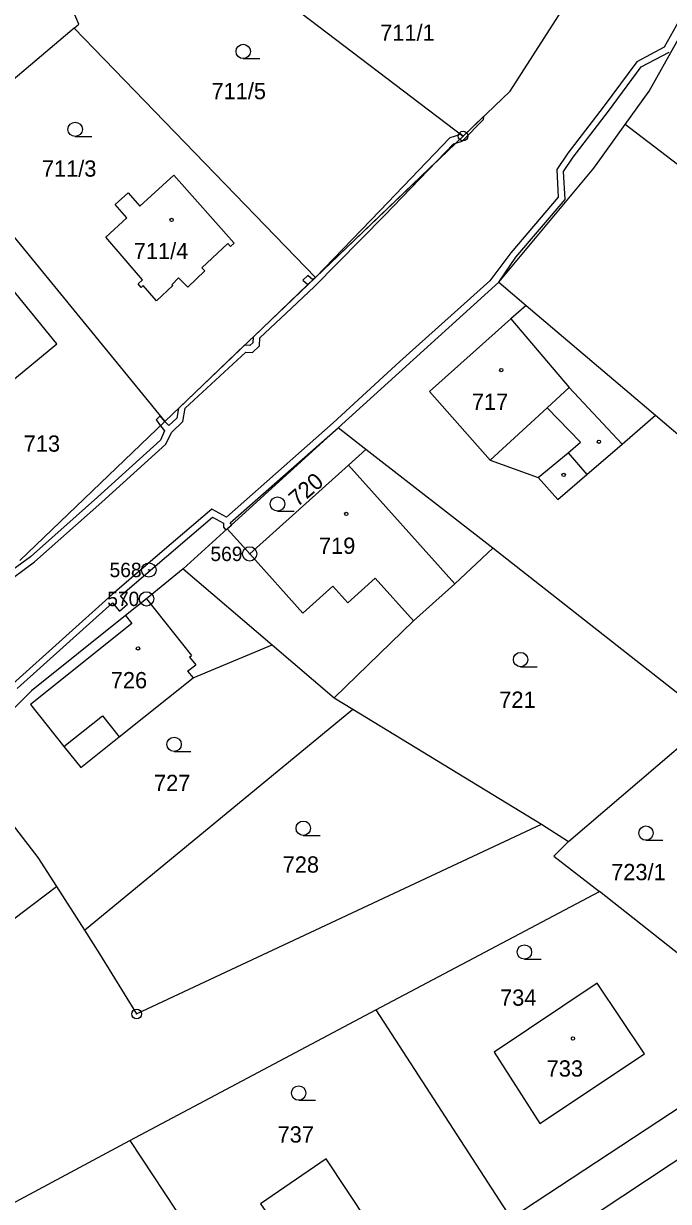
# Model space of a CAD drawing. Extents: x -562167 to -556918, y -1077891 to -1070763.
# Drawn here: x -558509.8 to -558442.5, y -1074168.9 to -1074045.9 of the extents above; entities that cross this region are included whole.
import ezdxf

# ---------------------------------------------------------------- set-up
doc = ezdxf.new("R2010")
doc.units = 0
for name, color, linetype in [('Hranice parcel', 7, 'Continuous'), ('Parcelní čísla', 7, 'Continuous'), ('Vnitřní kresba', 7, 'Continuous'), ('Věcná břemena k části', 7, 'Continuous'), ('Značky bodu BP', 7, 'Continuous'), ('Značky budov', 7, 'Continuous'), ('Značky kultur', 7, 'Continuous')]:
    doc.layers.add(name, color=color, linetype=linetype)

msp = doc.modelspace()

# ---------------------------------------------------------------- linework, layer by layer
at = {"layer": 'Hranice parcel'}
for p, q in [((-558504.53, -1074046.37), (-558518.85, -1074058.43)), ((-558479.36, -1074072.4), (-558504.53, -1074046.37)), ((-558479.36, -1074072.4), (-558463.94, -1074057.63)), ((-558518.85, -1074058.43), (-558495.07, -1074087.45)), ((-558495.07, -1074087.45), (-558479.36, -1074072.4)), ((-558460.22, -1074072.87), (-558476.98, -1074088.11)), ((-558460.22, -1074072.87), (-558457.36, -1074075.31)), ((-558457.36, -1074075.31), (-558443.86, -1074086.79)), ((-558510.2, -1074101.96), (-558495.07, -1074087.45)), ((-558476.98, -1074088.11), (-558488.55, -1074098.65)), ((-558474.08, -1074090.37), (-558476.98, -1074088.11)), ((-558460.85, -1074100.66), (-558474.08, -1074090.37)), ((-558488.55, -1074098.65), (-558493.14, -1074102.82)), ((-558438.83, -1074117.96), (-558460.85, -1074100.66)), ((-558493.14, -1074102.82), (-558483.85, -1074110.77)), ((-558483.85, -1074110.77), (-558477.39, -1074116.29)), ((-558477.39, -1074116.29), (-558475.43, -1074117.49)), ((-558503.45, -1074140.56), (-558475.43, -1074117.49)), ((-558475.43, -1074117.49), (-558455.77, -1074129.5)), ((-558455.77, -1074129.5), (-558452.94, -1074131.31)), ((-558506.36, -1074135.99), (-558503.45, -1074140.56)), ((-558473.04, -1074148.86), (-558449.71, -1074136.51)), ((-558430.4, -1074151.84), (-558449.71, -1074136.51)), ((-558498.72, -1074162.51), (-558473.04, -1074148.86)), ((-558473.04, -1074148.86), (-558458.96, -1074170.63)), ((-558458.96, -1074170.63), (-558430.4, -1074151.84)), ((-558456.42, -1074174.34), (-558426.68, -1074154.67)), ((-558520.86, -1074174.38), (-558498.72, -1074162.51)), ((-558498.72, -1074162.51), (-558483, -1074186.39))]:
    msp.add_line(p, q, dxfattribs=at)
for points in [[(-558463.94, -1074057.63), (-558459.03, -1074052.93), (-558449.24, -1074037.67), (-558444.63, -1074028.15)], [(-558493.98, -1074033.22), (-558482.6, -1074043.39), (-558463.94, -1074057.63)], [(-558504.53, -1074046.37), (-558504.04, -1074045.95), (-558506.35, -1074040.56)], [(-558447.01, -1074056.43), (-558444.52, -1074052.95), (-558438.75, -1074042.6), (-558438.26, -1074041.55)], [(-558460.22, -1074072.87), (-558450.28, -1074060.99), (-558447.01, -1074056.43)], [(-558410.6, -1074103.32), (-558428.61, -1074087.89), (-558420.55, -1074076.56), (-558436.68, -1074064.33), (-558447.01, -1074056.43)], [(-558494.24, -1074073.25), (-558495.93, -1074074.84), (-558497.33, -1074073.25), (-558497.54, -1074073.43), (-558497.85, -1074073.06), (-558497.39, -1074072.65), (-558501.24, -1074068.18), (-558499.03, -1074066.16), (-558500.26, -1074064.78), (-558498.9, -1074063.57), (-558497.67, -1074064.94), (-558494.14, -1074061.72), (-558487.84, -1074068.83), (-558488.2, -1074069.16), (-558488.5, -1074068.85), (-558491.2, -1074071.4), (-558490.9, -1074071.71), (-558492.68, -1074073.4), (-558493.63, -1074072.45), (-558494.34, -1074073.15), (-558494.24, -1074073.25)], [(-558520.15, -1074072.93), (-558519.41, -1074073.85), (-558524.41, -1074077.91), (-558522.76, -1074079.92), (-558522.95, -1074080.08), (-558516.62, -1074087.78), (-558506.33, -1074079.31), (-558512.65, -1074071.63), (-558515.03, -1074068.78)], [(-558457.36, -1074075.31), (-558458.94, -1074076.72), (-558467.46, -1074084.32), (-558461.1, -1074091.47), (-558456.11, -1074093.3), (-558454.04, -1074095.58), (-558451.01, -1074092.97), (-558447.34, -1074089.8), (-558443.86, -1074086.79)], [(-558443.86, -1074086.79), (-558433.98, -1074095.19), (-558411.79, -1074113.59)], [(-558474.08, -1074090.37), (-558475.91, -1074092.01), (-558486.21, -1074101.26), (-558488.55, -1074098.65)], [(-558477.39, -1074116.29), (-558469.1, -1074108.25), (-558464.8, -1074104.38), (-558460.85, -1074100.66)], [(-558493.14, -1074102.82), (-558496.98, -1074105.96), (-558499.17, -1074107.7)], [(-558499.17, -1074107.7), (-558508.98, -1074115.58), (-558516.19, -1074122.81)], [(-558499.17, -1074107.7), (-558498.5, -1074108.54), (-558509.1, -1074116.99), (-558505.6, -1074121.38), (-558503.85, -1074123.57), (-558499.82, -1074120.36), (-558492.12, -1074114.22), (-558483.85, -1074110.77)], [(-558452.94, -1074131.31), (-558438.12, -1074118.61), (-558438.83, -1074117.96)], [(-558513.01, -1074126.92), (-558508.33, -1074132.96), (-558506.36, -1074135.99)], [(-558503.45, -1074140.56), (-558501.88, -1074143.02), (-558498.01, -1074149.31), (-558455.77, -1074129.5)], [(-558452.94, -1074131.31), (-558454.46, -1074132.83), (-558449.71, -1074136.51)], [(-558531.92, -1074156.5), (-558521.73, -1074148.8), (-558518.98, -1074146.71), (-558518.11, -1074147.85), (-558512.56, -1074143.64), (-558513.98, -1074141.77), (-558509.95, -1074138.72), (-558506.36, -1074135.99)], [(-558455.92, -1074160.76), (-558445.02, -1074153.47), (-558449.94, -1074146.1), (-558460.7, -1074153.31), (-558455.92, -1074160.76)], [(-558480.2, -1074180), (-558471.66, -1074174.35), (-558478.22, -1074164.45), (-558485.07, -1074169.15), (-558483.98, -1074170.75), (-558485.58, -1074171.84), (-558480.2, -1074180)]]:
    msp.add_lwpolyline(points, dxfattribs=at)
at = {"layer": 'Vnitřní kresba'}
for p, q in [((-558458.94, -1074076.72), (-558452.85, -1074083.87)), ((-558455.16, -1074086), (-558452.85, -1074083.87)), ((-558452.85, -1074083.87), (-558447.34, -1074089.8)), ((-558461.1, -1074091.47), (-558455.16, -1074086)), ((-558455.16, -1074086), (-558451.68, -1074089.58)), ((-558452.97, -1074090.7), (-558451.68, -1074089.58)), ((-558456.11, -1074093.3), (-558452.97, -1074090.7)), ((-558452.97, -1074090.7), (-558451.01, -1074092.97)), ((-558475.91, -1074092.01), (-558464.8, -1074104.38)), ((-558486.21, -1074101.26), (-558480.65, -1074107.45)), ((-558480.65, -1074107.45), (-558477.53, -1074104.64)), ((-558477.53, -1074104.64), (-558475.98, -1074106.37)), ((-558475.98, -1074106.37), (-558473.11, -1074103.79)), ((-558473.11, -1074103.79), (-558469.1, -1074108.25)), ((-558496.98, -1074105.96), (-558492.27, -1074111.87)), ((-558492.49, -1074112.04), (-558492.27, -1074111.87)), ((-558492.49, -1074112.04), (-558491.85, -1074112.85)), ((-558492.69, -1074113.51), (-558491.85, -1074112.85)), ((-558492.69, -1074113.51), (-558492.12, -1074114.22)), ((-558505.6, -1074121.38), (-558501.57, -1074118.17)), ((-558501.57, -1074118.17), (-558499.82, -1074120.36))]:
    msp.add_line(p, q, dxfattribs=at)
at = {"layer": 'Věcná břemena k části'}
for points in [[(-558439.52, -1074042.18), (-558442.95, -1074048.35), (-558445.81, -1074049.86), (-558449.31, -1074054.6), (-558453, -1074059.42), (-558454.17, -1074061.12), (-558454, -1074064), (-558458.97, -1074069.84), (-558461.16, -1074072.74), (-558470.54, -1074081.18), (-558477.51, -1074087.58), (-558488.65, -1074097.44), (-558490.18, -1074096.59), (-558495.36, -1074101.01), (-558500.58, -1074105.5), (-558510.95, -1074114.83)], [(-558510.47, -1074115.33), (-558500.54, -1074106.38), (-558499.81, -1074107.24), (-558498.97, -1074106.53), (-558499.7, -1074105.66), (-558494.9, -1074101.55), (-558490.1, -1074097.43), (-558488.95, -1074098.06), (-558488.96, -1074098.47), (-558488.69, -1074098.78), (-558488.55, -1074098.65), (-558488.08, -1074098.22), (-558488.25, -1074098.02), (-558476.98, -1074088.11), (-558460.22, -1074072.87), (-558458.43, -1074070.28), (-558453.28, -1074064.24), (-558453.45, -1074061.32), (-558452.44, -1074059.83), (-558448.75, -1074055.02), (-558445.35, -1074050.4), (-558442.44, -1074048.88)], [(-558512.05, -1074104.59), (-558508.66, -1074102.1), (-558501.63, -1074095.86), (-558494.95, -1074089.82), (-558494.39, -1074088.58), (-558493.19, -1074087.44), (-558492.94, -1074086.06), (-558486.6, -1074080.18), (-558485.92, -1074080.23), (-558485.19, -1074079.55), (-558485.16, -1074078.71), (-558482.44, -1074076.17), (-558479.44, -1074073.35), (-558472.13, -1074065.91), (-558466.68, -1074060.25), (-558479.36, -1074072.4), (-558479.63, -1074072.65), (-558480.13, -1074073.14), (-558485.85, -1074078.62), (-558485.88, -1074079.23), (-558486.18, -1074079.51), (-558486.74, -1074079.47), (-558493.66, -1074086.09), (-558493.83, -1074087.09), (-558494.64, -1074087.85), (-558495.07, -1074087.45), (-558495.51, -1074087.88), (-558495.09, -1074088.42), (-558495.53, -1074089.4), (-558502.09, -1074095.34), (-558509.1, -1074101.56), (-558512.36, -1074103.95)]]:
    msp.add_lwpolyline(points, dxfattribs=at)
for points in [[(-558461.8, -1074055.89), (-558461.78, -1074055.56), (-558463.94, -1074057.63), (-558464.71, -1074058.37), (-558464.05, -1074058.16)], [(-558465.31, -1074057.82), (-558472.63, -1074065.43), (-558479.36, -1074072.4), (-558466.68, -1074060.25), (-558464.93, -1074058.44), (-558464.71, -1074058.37), (-558463.94, -1074057.63), (-558464.26, -1074057.38), (-558464.42, -1074057.55)], [(-558480.65, -1074072.68), (-558480.13, -1074073.14), (-558479.63, -1074072.65), (-558480.16, -1074072.19)], [(-558495.99, -1074087.27), (-558495.51, -1074087.88), (-558495.07, -1074087.45), (-558495.56, -1074086.86)]]:
    msp.add_lwpolyline(points, close=True, dxfattribs=at)
at = {"layer": 'Značky bodu BP'}
for centre, radius in [((-558463.94, -1074057.63), 0.5), ((-558463.94, -1074057.63), 0.0303), ((-558486.21, -1074101.26), 0.75), ((-558496.74, -1074102.94), 0.75), ((-558486.21, -1074101.26), 0.03), ((-558496.74, -1074102.94), 0.03), ((-558496.98, -1074105.96), 0.75), ((-558496.98, -1074105.96), 0.03), ((-558498.01, -1074149.31), 0.5), ((-558498.01, -1074149.31), 0.0303)]:
    msp.add_circle(centre, radius, dxfattribs=at)
at = {"layer": 'Značky budov'}
for centre in [(-558494.37, -1074066.38), (-558459.95, -1074082.07), (-558449.76, -1074089.55), (-558453.44, -1074093.02), (-558476.14, -1074097.09), (-558497.87, -1074111.14), (-558452.47, -1074151.87)]:
    msp.add_circle(centre, 0.175, dxfattribs=at)
at = {"layer": 'Značky kultur'}
for p, q in [((-558486.89, -1074049.54), (-558485.14, -1074049.54)), ((-558504.43, -1074057.68), (-558502.68, -1074057.68)), ((-558483.31, -1074096.8), (-558481.56, -1074096.8)), ((-558457.94, -1074113.05), (-558456.19, -1074113.05)), ((-558494.1, -1074121.9), (-558492.35, -1074121.9)), ((-558480.62, -1074130.66), (-558478.87, -1074130.66)), ((-558444.85, -1074131.17), (-558443.1, -1074131.17)), ((-558457.54, -1074143.59), (-558455.79, -1074143.59)), ((-558481.1, -1074158.32), (-558479.35, -1074158.32))]:
    msp.add_line(p, q, dxfattribs=at)
for centre in [(-558486.89, -1074048.79), (-558504.43, -1074056.93), (-558483.31, -1074096.05), (-558457.94, -1074112.3), (-558494.1, -1074121.15), (-558480.62, -1074129.91), (-558444.85, -1074130.42), (-558457.54, -1074142.84), (-558481.1, -1074157.57)]:
    msp.add_circle(centre, 0.75, dxfattribs=at)

# ---------------------------------------------------------------- texts
at = {"layer": 'Parcelní čísla'}
for s, p in [('711/1', (-558472.59, -1074047.68)), ('711/5', (-558490.2, -1074053.78)), ('711/3', (-558507.9, -1074061.87)), ('711/4', (-558498.31, -1074070.48)), ('717', (-558463.02, -1074086.22)), ('713', (-558509.8, -1074090.59)), ('719', (-558478.98, -1074101.26)), ('726', (-558500.71, -1074115.3)), ('721', (-558460.16, -1074117.34)), ('727', (-558496.2, -1074126.03)), ('728', (-558482.77, -1074134.55)), ('723/1', (-558448.48, -1074135.34)), ('734', (-558460.08, -1074148.45)), ('733', (-558455.21, -1074155.85)), ('737', (-558483.3, -1074162.74))]:
    msp.add_text(s, height=1.7, dxfattribs=at).set_placement(p)
msp.add_text('720', height=1.7, rotation=41, dxfattribs=at).set_placement((-558481.22, -1074096.43))
at = {"layer": 'Značky bodu BP'}
for s, p in [('569', (-558490.31, -1074102.01)), ('568', (-558500.84, -1074103.69)), ('570', (-558501.08, -1074106.71))]:
    msp.add_text(s, height=1.5, dxfattribs=at).set_placement(p)

doc.saveas('drawing.dxf')
